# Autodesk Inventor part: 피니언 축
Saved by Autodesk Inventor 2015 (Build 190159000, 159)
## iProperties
Created: 2024-11
Part Number: 피니언 축
Material: 일반
Document SubType Name: Modeling
Designer: 102-5
Density: 1 g/cm^3
Appearance: 기본값
Author: 102-5
Author: jhkim
Creation Date: 2024-10-25
Sending System: Autodesk Inventor 2025
Preprocessor: ST-DEVELOPER v20
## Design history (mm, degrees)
node "피니언 축1"
node "솔리드1"
node "기준1"
